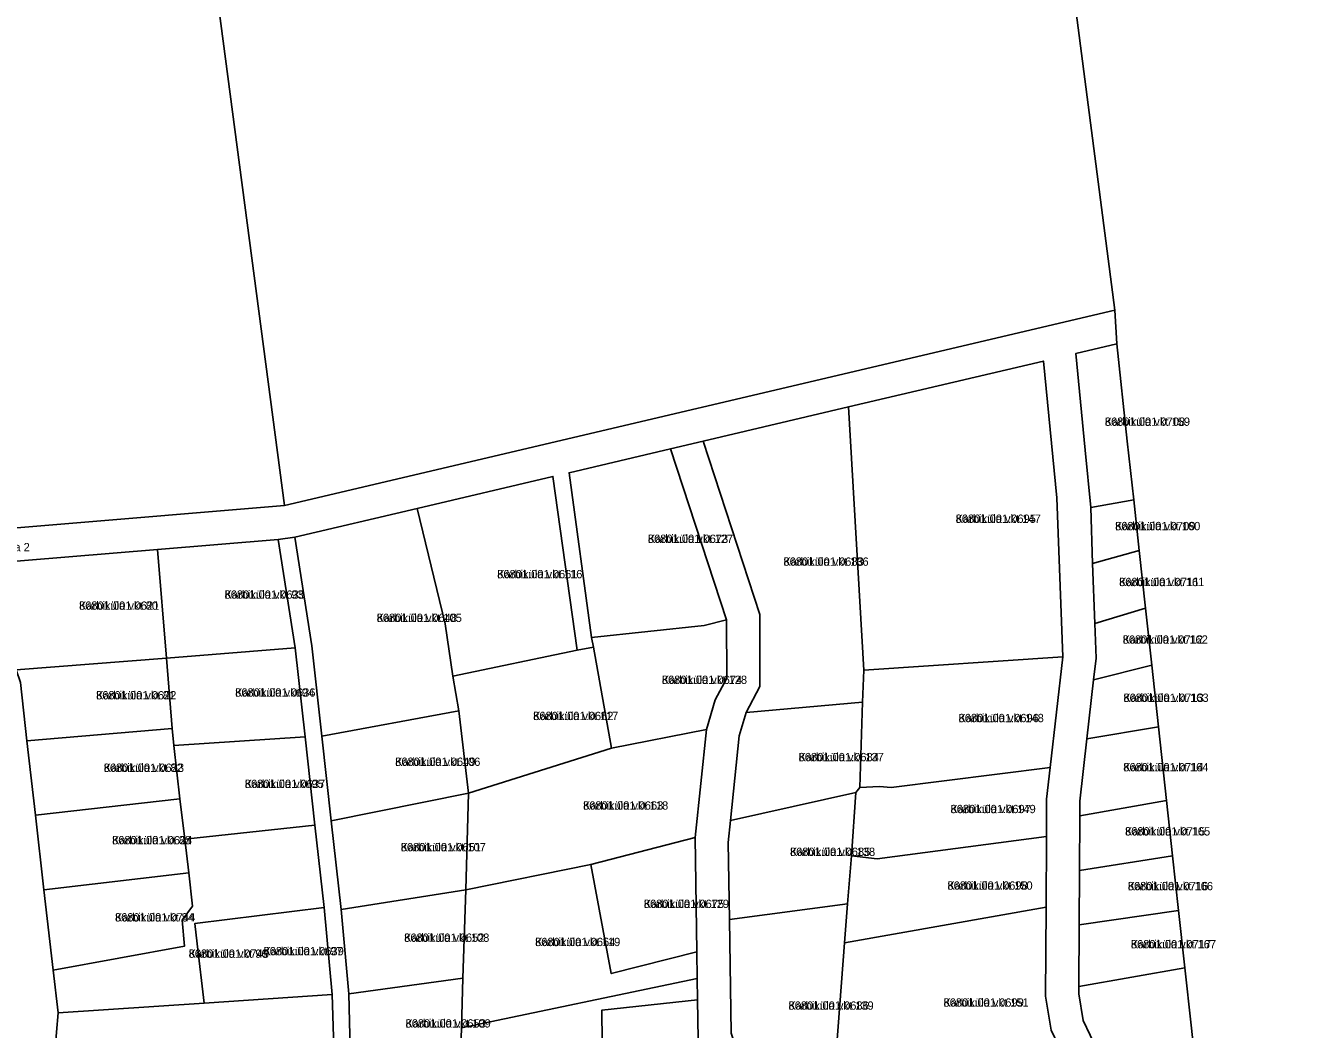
# Model space of a CAD drawing. Extents: x 484607 to 525396, y 6554521 to 6586559.
# Drawn here: x 517147.5 to 517380.7, y 6565444.8 to 6565625.8 of the extents above; entities that cross this region are included whole.
import ezdxf

# ---------------------------------------------------------------- set-up
doc = ezdxf.new("R2010")
doc.units = 0
for name, color, linetype in [('L_AADRESS', 7, 'Continuous'), ('PIIR', 7, 'Continuous'), ('TUNNUS', 7, 'Continuous')]:
    doc.layers.add(name, color=color, linetype=linetype)

msp = doc.modelspace()

# ---------------------------------------------------------------- linework, layer by layer
at = {"layer": 'PIIR'}
for points in [[(517065.3, 6565905.83), (516891.5, 6566178.94), (516912.53, 6566178.83), (516942.14, 6566178.23), (517138.32, 6565871.47), (517164.4, 6565732.41), (517178.95, 6565654.98), (517194.19, 6565539.27), (516980.7, 6565521.48), (516945.1, 6565531.21), (516969.03, 6565583.85), (517062.63, 6565789.32)], [(517178.95, 6565654.98), (517164.4, 6565732.41), (517173.19, 6565734.4), (517186.94, 6565743.73), (517195.24, 6565753.21), (517205.45, 6565769.63), (517211.71, 6565778.25), (517217.71, 6565783.01), (517225.03, 6565786.18), (517210.49, 6565692.74), (517256.92, 6565698.76), (517326.68, 6565708.93), (517344.15, 6565574.52), (517194.19, 6565539.27)], [(517337.11, 6565566.71), (517344.46, 6565568.44), (517346.37, 6565550.88), (517347.53, 6565540.29), (517339.81, 6565538.89), (517338.8, 6565549.24)], [(517296.05, 6565557.06), (517331.22, 6565565.33), (517333.68, 6565540.66), (517334.72, 6565511.96), (517298.79, 6565509.55)], [(517269.78, 6565550.86), (517296.05, 6565557.06), (517298.79, 6565509.55), (517298.56, 6565503.79), (517277.54, 6565501.89), (517280.06, 6565506.58), (517280.02, 6565519.6)], [(517245.6, 6565545.18), (517263.92, 6565549.46), (517274.03, 6565518.63), (517269.97, 6565517.62), (517249.67, 6565515.43)], [(517218.18, 6565538.74), (517242.67, 6565544.5), (517247.04, 6565513.14), (517224.58, 6565508.45), (517223.23, 6565517.88)], [(517196.05, 6565533.54), (517218.18, 6565538.74), (517223.23, 6565517.88), (517224.58, 6565508.45), (517225.66, 6565502.19), (517200.95, 6565497.64), (517199.15, 6565513.91)], [(517339.81, 6565538.89), (517347.53, 6565540.29), (517348.53, 6565531.14), (517340.12, 6565528.8)], [(517171.3, 6565531.33), (517193.08, 6565533.15), (517196.16, 6565513.58), (517172.89, 6565511.73)], [(517139.22, 6565528.66), (517171.3, 6565531.33), (517172.89, 6565511.73), (517145.75, 6565509.58)], [(517340.12, 6565528.8), (517348.53, 6565531.14), (517349.66, 6565520.75), (517340.51, 6565517.96)], [(517340.51, 6565517.96), (517349.66, 6565520.75), (517350.78, 6565510.46), (517340.29, 6565507.83), (517340.74, 6565511.73)], [(517249.67, 6565515.43), (517269.97, 6565517.62), (517274.03, 6565518.63), (517274.05, 6565508.08), (517271.96, 6565504.18), (517270.41, 6565498.86), (517253.24, 6565495.49), (517249.99, 6565513.72)], [(517172.89, 6565511.73), (517196.16, 6565513.58), (517197.94, 6565497.52), (517174.21, 6565495.96), (517173.95, 6565498.99)], [(517224.58, 6565508.45), (517247.04, 6565513.14), (517249.99, 6565513.72), (517253.24, 6565495.49), (517227.41, 6565487.37), (517225.66, 6565502.19)], [(517145.75, 6565509.58), (517172.89, 6565511.73), (517173.95, 6565498.99), (517147.72, 6565496.8), (517146.52, 6565507.34)], [(517298.79, 6565509.55), (517334.72, 6565511.96), (517332.46, 6565492), (517303.73, 6565488.37), (517301.65, 6565488.57), (517298.06, 6565488.36), (517298.56, 6565503.79)], [(517340.29, 6565507.83), (517350.78, 6565510.46), (517352, 6565499.3), (517339.08, 6565497.17)], [(517277.54, 6565501.89), (517298.56, 6565503.79), (517298.06, 6565488.36), (517297.37, 6565487.48), (517274.72, 6565482.43), (517276.32, 6565497.69)], [(517200.95, 6565497.64), (517225.66, 6565502.19), (517227.41, 6565487.37), (517202.64, 6565482.34)], [(517339.08, 6565497.17), (517352, 6565499.3), (517353.45, 6565486.02), (517337.79, 6565483.28), (517337.81, 6565485.93)], [(517147.72, 6565496.8), (517173.95, 6565498.99), (517174.21, 6565495.96), (517175.34, 6565486.34), (517149.25, 6565483.39)], [(517174.21, 6565495.96), (517197.94, 6565497.52), (517199.71, 6565481.57), (517176.2, 6565479.04), (517175.34, 6565486.34)], [(517227.41, 6565487.37), (517253.24, 6565495.49), (517270.41, 6565498.86), (517268.37, 6565479.36), (517249.51, 6565474.49), (517226.96, 6565469.91)], [(517297.37, 6565487.48), (517298.06, 6565488.36), (517301.65, 6565488.57), (517303.73, 6565488.37), (517332.46, 6565492), (517331.81, 6565486.28), (517331.77, 6565479.54), (517301.21, 6565475.48), (517296.6, 6565476.05)], [(517274.72, 6565482.43), (517297.37, 6565487.48), (517296.6, 6565476.05), (517295.86, 6565467.39), (517274.53, 6565464.55), (517274.31, 6565478.44)], [(517149.25, 6565483.39), (517175.34, 6565486.34), (517176.2, 6565479.04), (517176.92, 6565472.99), (517150.79, 6565469.89)], [(517202.64, 6565482.34), (517227.41, 6565487.37), (517226.96, 6565469.91), (517204.42, 6565466.35)], [(517337.79, 6565483.28), (517353.45, 6565486.02), (517354.54, 6565476.06), (517337.74, 6565473.39)], [(517176.2, 6565479.04), (517199.71, 6565481.57), (517201.36, 6565466.7), (517178, 6565463.81), (517178.43, 6565460.17), (517179.69, 6565449.48), (517153.32, 6565447.7), (517152.44, 6565455.4), (517176.18, 6565459.76), (517175.73, 6565464.44), (517177.63, 6565466.96), (517176.92, 6565472.99)], [(517249.51, 6565474.49), (517268.37, 6565479.36), (517268.66, 6565458.74), (517253.21, 6565454.8)], [(517296.6, 6565476.05), (517301.21, 6565475.48), (517331.77, 6565479.54), (517331.7, 6565466.78), (517295.33, 6565460.32), (517295.86, 6565467.39)], [(517337.74, 6565473.39), (517354.54, 6565476.06), (517355.62, 6565466.19), (517337.69, 6565463.6)], [(517226.96, 6565469.91), (517249.51, 6565474.49), (517253.21, 6565454.8), (517268.66, 6565458.74), (517268.72, 6565453.92), (517226.14, 6565445.02), (517226.44, 6565453.98)], [(517150.79, 6565469.89), (517176.92, 6565472.99), (517177.63, 6565466.96), (517175.73, 6565464.44), (517176.18, 6565459.76), (517152.44, 6565455.4)], [(517204.42, 6565466.35), (517226.96, 6565469.91), (517226.44, 6565453.98), (517205.84, 6565451.13)], [(517178, 6565463.81), (517201.36, 6565466.7), (517202.84, 6565451.04), (517179.69, 6565449.48), (517178.43, 6565460.17)], [(517274.53, 6565464.55), (517295.86, 6565467.39), (517295.33, 6565460.32), (517293.29, 6565433.3), (517279.99, 6565428.81), (517274.86, 6565444.02)], [(517295.33, 6565460.32), (517331.7, 6565466.78), (517331.62, 6565450.69), (517332.63, 6565444.55), (517333.93, 6565441.79), (517312.77, 6565436.12), (517293.11, 6565430.86), (517293.29, 6565433.3)], [(517337.69, 6565463.6), (517355.62, 6565466.19), (517356.75, 6565455.84), (517337.63, 6565452.48)], [(517337.63, 6565452.48), (517356.75, 6565455.84), (517357.88, 6565445.46), (517361.94, 6565408.22), (517356.89, 6565407.25), (517340.94, 6565441.01), (517338.41, 6565446.35), (517337.62, 6565451.16)], [(517205.84, 6565451.13), (517226.44, 6565453.98), (517226.14, 6565445.02), (517225.96, 6565439.42), (517206.19, 6565436.13)], [(517226.14, 6565445.02), (517268.72, 6565453.92), (517268.77, 6565450.06), (517251.53, 6565448.2), (517251.66, 6565431.13), (517250.33, 6565430.79), (517229.73, 6565426.03), (517225.96, 6565439.42)], [(517153.05, 6565444.2), (517153.32, 6565447.7), (517179.69, 6565449.48), (517202.84, 6565451.04), (517203.27, 6565437.6), (517203.07, 6565434.8), (517179.53, 6565435.1), (517152.38, 6565435.44)], [(517251.53, 6565448.2), (517268.77, 6565450.06), (517268.87, 6565442.98), (517275.6, 6565423.05), (517268.94, 6565420.68), (517254.74, 6565415.72), (517251.66, 6565431.13)]]:
    msp.add_lwpolyline(points, close=True, dxfattribs=at)
for points in [[(517389.61, 6565141.22), (517372.92, 6565307.66), (517371.53, 6565320.36), (517365.62, 6565374.54), (517363.6, 6565393.06), (517361.94, 6565408.22), (517357.88, 6565445.46), (517356.75, 6565455.84), (517355.62, 6565466.19), (517354.54, 6565476.06), (517353.45, 6565486.02), (517352, 6565499.3), (517350.78, 6565510.46), (517349.66, 6565520.75), (517348.53, 6565531.14), (517347.53, 6565540.29), (517346.37, 6565550.88), (517344.46, 6565568.44), (517344.15, 6565574.52), (517326.68, 6565708.93), (517381.83, 6565717.8)], [(516980.7, 6565521.48), (517194.19, 6565539.27), (517344.15, 6565574.52), (517344.46, 6565568.44), (517337.11, 6565566.71), (517338.8, 6565549.24), (517339.81, 6565538.89), (517340.12, 6565528.8), (517340.51, 6565517.96), (517340.74, 6565511.73), (517340.29, 6565507.83), (517339.08, 6565497.17), (517337.81, 6565485.93), (517337.79, 6565483.28), (517337.74, 6565473.39), (517337.69, 6565463.6), (517337.63, 6565452.48), (517337.62, 6565451.16), (517338.41, 6565446.35), (517340.94, 6565441.01)], [(517332.63, 6565444.55), (517331.62, 6565450.69), (517331.7, 6565466.78), (517331.77, 6565479.54), (517331.81, 6565486.28), (517332.46, 6565492), (517334.72, 6565511.96), (517333.68, 6565540.66), (517331.22, 6565565.33), (517296.05, 6565557.06), (517269.78, 6565550.86), (517263.92, 6565549.46), (517245.6, 6565545.18), (517249.67, 6565515.43), (517249.99, 6565513.72), (517247.04, 6565513.14), (517242.67, 6565544.5), (517218.18, 6565538.74), (517196.05, 6565533.54), (517193.08, 6565533.15), (517171.3, 6565531.33), (517139.22, 6565528.66)], [(517268.87, 6565442.98), (517268.77, 6565450.06), (517268.72, 6565453.92), (517268.66, 6565458.74), (517268.37, 6565479.36), (517270.41, 6565498.86), (517271.96, 6565504.18), (517274.05, 6565508.08), (517274.03, 6565518.63), (517263.92, 6565549.46), (517269.78, 6565550.86), (517280.02, 6565519.6), (517280.06, 6565506.58), (517277.54, 6565501.89), (517276.32, 6565497.69), (517274.72, 6565482.43), (517274.31, 6565478.44), (517274.53, 6565464.55), (517274.86, 6565444.02)], [(517203.27, 6565437.6), (517202.84, 6565451.04), (517201.36, 6565466.7), (517199.71, 6565481.57), (517197.94, 6565497.52), (517196.16, 6565513.58), (517193.08, 6565533.15), (517196.05, 6565533.54), (517199.15, 6565513.91), (517200.95, 6565497.64), (517202.64, 6565482.34), (517204.42, 6565466.35), (517205.84, 6565451.13), (517206.19, 6565436.13)], [(517146.52, 6565507.34), (517147.72, 6565496.8), (517149.25, 6565483.39), (517150.79, 6565469.89), (517152.44, 6565455.4), (517153.32, 6565447.7), (517153.05, 6565444.2)]]:
    msp.add_lwpolyline(points, dxfattribs=at)

# ---------------------------------------------------------------- texts
at = {"layer": 'L_AADRESS'}
for s, p in [('Karbiküla vkt 159', (517342.32, 6565553.64)), ('Karbiküla vkt 147', (517315.38, 6565536.13)), ('Karbiküla vkt 160', (517344.17, 6565534.8)), ('Karbiküla vkt 127', (517259.82, 6565532.51)), ('Karbiküla üldmaa 2', (517131.06, 6565531)), ('Karbiküla vkt 136', (517284.29, 6565528.39)), ('Karbiküla vkt 116', (517232.61, 6565526.13)), ('Karbiküla vkt 161', (517344.89, 6565524.71)), ('Karbiküla vkt 93', (517183.39, 6565522.44)), ('Karbiküla vkt 80', (517157.11, 6565520.45)), ('Karbiküla vkt 105', (517210.85, 6565518.24)), ('Karbiküla vkt 162', (517345.54, 6565514.32)), ('Karbiküla vkt 128', (517262.34, 6565507.06)), ('Karbiküla vkt 94', (517185.3, 6565504.77)), ('Karbiküla vkt 81', (517160.19, 6565504.27)), ('Karbiküla vkt 163', (517345.67, 6565503.82)), ('Karbiküla vkt 117', (517239.1, 6565500.54)), ('Karbiküla vkt 148', (517315.91, 6565500.16)), ('Karbiküla vkt 137', (517287.03, 6565493.11)), ('Karbiküla vkt 82', (517161.57, 6565491.19)), ('Karbiküla vkt 106', (517214.19, 6565492.27)), ('Karbiküla vkt 164', (517345.65, 6565491.29)), ('Karbiküla vkt 95', (517187.04, 6565488.28)), ('Karbiküla vkt 118', (517248.11, 6565484.38)), ('Karbiküla vkt 149', (517314.46, 6565483.74)), ('Karbiküla vkt 165', (517345.96, 6565479.71)), ('Karbiküla vkt 83', (517163.08, 6565478.12)), ('Karbiküla vkt 107', (517215.19, 6565476.86)), ('Karbiküla vkt 138', (517285.47, 6565476.02)), ('Karbiküla vkt 150', (517313.9, 6565469.93)), ('Karbiküla vkt 166', (517346.47, 6565469.83)), ('Karbiküla vkt 129', (517259.08, 6565466.63)), ('Karbiküla vkt 84', (517163.6, 6565464.19)), ('Karbiküla vkt 108', (517215.81, 6565460.52)), ('Karbiküla vkt 97', (517190.42, 6565458.09)), ('Karbiküla vkt 119', (517239.45, 6565459.75)), ('Karbiküla vkt 167', (517347.02, 6565459.34)), ('Karbiküla vkt 96', (517176.9, 6565457.64)), ('Karbiküla vkt 151', (517313.19, 6565448.82)), ('Karbiküla vkt 139', (517285.2, 6565448.27)), ('Karbiküla vkt 109', (517216.06, 6565445.05))]:
    msp.add_text(s, height=1.5, dxfattribs=at).set_placement(p)
at = {"layer": 'TUNNUS'}
for s, p in [('86801:001:0708', (517342.32, 6565553.64)), ('86801:001:0695', (517315.38, 6565536.13)), ('86801:001:0709', (517344.17, 6565534.8)), ('86801:001:0673', (517259.82, 6565532.51)), ('86801:001:0683', (517284.29, 6565528.39)), ('86801:001:0661', (517232.61, 6565526.13)), ('86801:001:0711', (517344.89, 6565524.71)), ('86801:001:0635', (517183.39, 6565522.44)), ('86801:001:0621', (517157.11, 6565520.45)), ('86801:001:0648', (517210.85, 6565518.24)), ('86801:001:0712', (517345.54, 6565514.32)), ('86801:001:0674', (517262.34, 6565507.06)), ('86801:001:0636', (517185.3, 6565504.77)), ('86801:001:0622', (517160.19, 6565504.27)), ('86801:001:0713', (517345.67, 6565503.82)), ('86801:001:0662', (517239.1, 6565500.54)), ('86801:001:0696', (517315.91, 6565500.16)), ('86801:001:0684', (517287.03, 6565493.11)), ('86801:001:0623', (517161.57, 6565491.19)), ('86801:001:0649', (517214.19, 6565492.27)), ('86801:001:0714', (517345.65, 6565491.29)), ('86801:001:0637', (517187.04, 6565488.28)), ('86801:001:0663', (517248.11, 6565484.38)), ('86801:001:0697', (517314.46, 6565483.74)), ('86801:001:0715', (517345.96, 6565479.71)), ('86801:001:0624', (517163.08, 6565478.12)), ('86801:001:0651', (517215.19, 6565476.86)), ('86801:001:0685', (517285.47, 6565476.02)), ('86801:001:0698', (517313.9, 6565469.93)), ('86801:001:0716', (517346.47, 6565469.83)), ('86801:001:0675', (517259.08, 6565466.63)), ('86801:001:0744', (517163.6, 6565464.19)), ('86801:001:0652', (517215.81, 6565460.52)), ('86801:001:0639', (517190.42, 6565458.09)), ('86801:001:0664', (517239.45, 6565459.75)), ('86801:001:0717', (517347.02, 6565459.34)), ('86801:001:0745', (517176.9, 6565457.64)), ('86801:001:0699', (517313.19, 6565448.82)), ('86801:001:0686', (517285.2, 6565448.27)), ('86801:001:0653', (517216.06, 6565445.05))]:
    msp.add_text(s, height=1.5, dxfattribs=at).set_placement(p)

doc.saveas('drawing.dxf')
